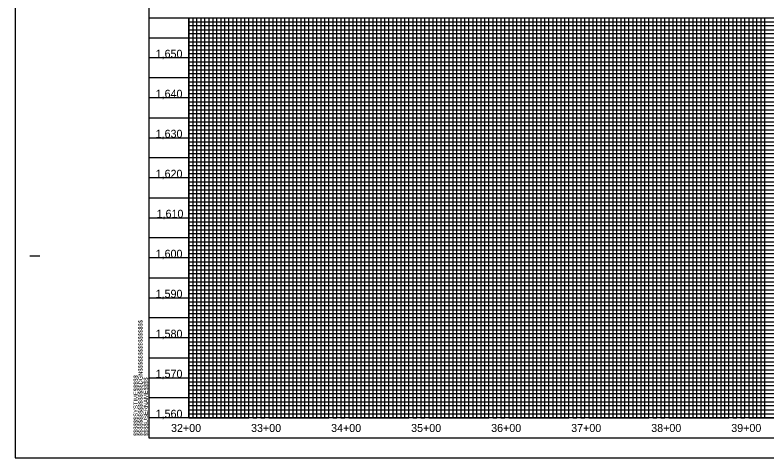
# Model space of a CAD drawing. Extents: x 502400 to 509344, y 448070 to 484209.
# Drawn here: x 505602 to 506542, y 483109 to 483662 of the extents above; entities that cross this region are included whole.
import ezdxf

# ---------------------------------------------------------------- set-up
doc = ezdxf.new("R2010")
doc.units = 0
for name, color, linetype in [('Exist Vertical Profile Vertical Axis Label', 7, 'Continuous'), ('Sheet Layout Profile Border Port 2', 7, 'Continuous'), ('Sheet Plot Border Outside CELL', 7, 'Continuous'), ('Sheet Profile CELL', 7, 'Continuous'), ('Sheet Profile Grid Major CELL', 7, 'Continuous'), ('Sheet Profile Grid Middle CELL', 7, 'Continuous'), ('Sheet Profile Grid Minor CELL', 7, 'Continuous')]:
    doc.layers.add(name, color=color, linetype=linetype)

msp = doc.modelspace()

# ---------------------------------------------------------------- linework, layer by layer
at = {"layer": 'Sheet Layout Profile Border Port 2'}
msp.add_lwpolyline([(505819.08, 483658.71), (507219.08, 483658.71), (507219.08, 483158.71), (505819.08, 483158.71)], close=True, dxfattribs=at)
at = {"layer": 'Sheet Plot Border Outside CELL'}
msp.add_lwpolyline([(505602.08, 483108.71), (507286.08, 483108.71), (507286.08, 484208.71), (505602.08, 484208.71)], close=True, dxfattribs=at)
at = {"layer": 'Sheet Profile CELL'}
for p, q in [((505769.08, 483658.71), (507269.08, 483658.71)), ((505620.58, 483361.21), (505633.08, 483361.21)), ((507269.08, 483158.71), (505769.08, 483158.71)), ((505769.08, 483133.71), (507269.08, 483133.71)), ((505769.08, 483133.71), (505769.08, 483133.71)), ((505769.08, 483133.71), (505769.08, 483133.71)), ((505769.08, 483133.71), (505769.08, 483133.71)), ((505769.08, 483133.71), (505769.08, 483133.71)), ((505769.08, 483133.71), (505769.08, 483133.71)), ((505769.08, 483133.71), (505769.08, 483133.71)), ((505769.08, 483133.71), (505769.08, 483133.71))]:
    msp.add_line(p, q, dxfattribs=at)
msp.add_lwpolyline([(507269.08, 484183.71), (505769.08, 484183.71), (505769.08, 483133.71), (507269.08, 483133.71)], close=True, dxfattribs=at)
msp.add_lwpolyline([(505806.58, 483133.71), (505806.58, 483133.71)], dxfattribs=at)
at = {"layer": 'Sheet Profile Grid Major CELL'}
for p, q in [((506269.08, 483658.71), (506319.08, 483658.71)), ((506369.08, 483658.71), (506419.08, 483658.71)), ((506469.08, 483658.71), (506519.08, 483658.71))]:
    msp.add_line(p, q, dxfattribs=at)
for points in [[(505819.08, 483658.71), (505819.08, 483158.71), (505869.08, 483158.71), (505869.08, 483658.71), (505919.08, 483658.71), (505919.08, 483158.71), (505969.08, 483158.71), (505969.08, 483658.71), (506019.08, 483658.71), (506019.08, 483158.71), (506069.08, 483158.71), (506069.08, 483658.71), (506119.08, 483658.71), (506119.08, 483158.71), (506169.08, 483158.71), (506169.08, 483658.71), (506219.08, 483658.71), (506219.08, 483158.71), (506269.08, 483158.71), (506269.08, 483658.71), (506319.08, 483658.71), (506319.08, 483158.71), (506369.08, 483158.71), (506369.08, 483658.71), (506419.08, 483658.71), (506419.08, 483158.71), (506469.08, 483158.71), (506469.08, 483658.71), (506519.08, 483658.71), (506519.08, 483158.71), (506569.08, 483158.71)], [(505819.08, 483658.71), (505819.08, 483158.71), (505869.08, 483158.71), (505869.08, 483658.71), (505919.08, 483658.71), (505919.08, 483158.71), (505969.08, 483158.71), (505969.08, 483658.71), (506019.08, 483658.71), (506019.08, 483158.71), (506069.08, 483158.71), (506069.08, 483658.71), (506119.08, 483658.71), (506119.08, 483158.71), (506169.08, 483158.71), (506169.08, 483658.71), (506219.08, 483658.71), (506219.08, 483158.71), (506269.08, 483158.71), (506269.08, 483658.71), (506319.08, 483658.71), (506319.08, 483158.71), (506369.08, 483158.71), (506369.08, 483658.71), (506419.08, 483658.71), (506419.08, 483158.71), (506469.08, 483158.71), (506469.08, 483658.71), (506519.08, 483658.71), (506519.08, 483158.71), (506569.08, 483158.71)], [(507269.08, 483608.71), (505769.08, 483608.71)], [(507269.08, 483558.71), (505769.08, 483558.71), (505769.08, 483508.71), (507269.08, 483508.71)], [(507269.08, 483458.71), (505769.08, 483458.71), (505769.08, 483408.71), (507269.08, 483408.71)], [(507269.08, 483358.71), (505769.08, 483358.71), (505769.08, 483308.71), (507269.08, 483308.71)], [(507269.08, 483258.71), (505769.08, 483258.71), (505769.08, 483258.71), (505769.08, 483208.71), (507269.08, 483208.71)], [(507269.08, 483158.71), (505769.08, 483158.71)]]:
    msp.add_lwpolyline(points, dxfattribs=at)
at = {"layer": 'Sheet Profile Grid Middle CELL'}
for points in [[(505794.08, 483658.71), (505844.08, 483658.71), (505844.08, 483158.71), (505894.08, 483158.71), (505894.08, 483658.71), (505944.08, 483658.71), (505944.08, 483158.71), (505994.08, 483158.71), (505994.08, 483658.71), (506044.08, 483658.71), (506044.08, 483158.71), (506094.08, 483158.71), (506094.08, 483658.71), (506144.08, 483658.71), (506144.08, 483158.71), (506194.08, 483158.71), (506194.08, 483658.71), (506244.08, 483658.71), (506244.08, 483158.71), (506294.08, 483158.71), (506294.08, 483658.71), (506344.08, 483658.71), (506344.08, 483158.71), (506394.08, 483158.71), (506394.08, 483158.71), (506394.08, 483658.71), (506444.08, 483658.71), (506444.08, 483158.71), (506494.08, 483158.71), (506494.08, 483658.71), (506544.08, 483658.71)], [(505769.08, 483633.71), (507269.08, 483633.71)], [(507269.08, 483583.71), (505769.08, 483583.71), (505769.08, 483533.71), (507269.08, 483533.71)], [(507269.08, 483483.71), (505769.08, 483483.71), (505769.08, 483433.71), (507269.08, 483433.71)], [(507269.08, 483383.71), (505769.08, 483383.71), (505769.08, 483333.71), (507269.08, 483333.71)], [(507269.08, 483283.71), (505769.08, 483283.71), (505769.08, 483233.71), (507269.08, 483233.71)], [(507269.08, 483183.71), (505769.08, 483183.71)]]:
    msp.add_lwpolyline(points, dxfattribs=at)
at = {"layer": 'Sheet Profile Grid Minor CELL'}
for p, q in [((505819.08, 483653.71), (507219.08, 483653.71)), ((507219.08, 483648.71), (505819.08, 483648.71)), ((505819.08, 483643.71), (507219.08, 483643.71)), ((507219.08, 483638.71), (505819.08, 483638.71)), ((505819.08, 483628.71), (507219.08, 483628.71)), ((507219.08, 483623.71), (505819.08, 483623.71)), ((505819.08, 483618.71), (507219.08, 483618.71)), ((507219.08, 483613.71), (505819.08, 483613.71)), ((505819.08, 483603.71), (507219.08, 483603.71)), ((507219.08, 483598.71), (505819.08, 483598.71)), ((505819.08, 483593.71), (507219.08, 483593.71)), ((507219.08, 483588.71), (505819.08, 483588.71)), ((505819.08, 483578.71), (507219.08, 483578.71)), ((507219.08, 483573.71), (505819.08, 483573.71)), ((505819.08, 483568.71), (507219.08, 483568.71)), ((507219.08, 483563.71), (505819.08, 483563.71)), ((505819.08, 483553.71), (507219.08, 483553.71)), ((507219.08, 483548.71), (505819.08, 483548.71)), ((505819.08, 483543.71), (507219.08, 483543.71)), ((507219.08, 483538.71), (505819.08, 483538.71)), ((505819.08, 483528.71), (507219.08, 483528.71)), ((507219.08, 483523.71), (505819.08, 483523.71)), ((505819.08, 483518.71), (507219.08, 483518.71)), ((507219.08, 483513.71), (505819.08, 483513.71)), ((505819.08, 483503.71), (507219.08, 483503.71)), ((507219.08, 483498.71), (505819.08, 483498.71)), ((505819.08, 483493.71), (507219.08, 483493.71)), ((507219.08, 483488.71), (505819.08, 483488.71)), ((505819.08, 483478.71), (507219.08, 483478.71)), ((507219.08, 483473.71), (505819.08, 483473.71)), ((505819.08, 483468.71), (507219.08, 483468.71)), ((507219.08, 483463.71), (505819.08, 483463.86)), ((505819.08, 483453.71), (507219.08, 483453.71)), ((507219.08, 483448.71), (505819.08, 483448.71)), ((505819.08, 483443.71), (507219.08, 483443.71)), ((507219.08, 483438.71), (505819.08, 483438.71)), ((505819.08, 483428.71), (507219.08, 483428.71)), ((507219.08, 483423.71), (505819.08, 483423.71)), ((505819.08, 483418.71), (507219.08, 483418.71)), ((507219.08, 483413.71), (505819.08, 483413.71)), ((505819.08, 483403.71), (507219.08, 483403.71)), ((507219.08, 483398.71), (505819.08, 483398.71)), ((505819.08, 483393.71), (507219.08, 483393.71)), ((507219.08, 483388.71), (505819.08, 483388.71)), ((505819.08, 483378.71), (507219.08, 483378.71)), ((507219.08, 483373.71), (505819.08, 483373.71)), ((505819.08, 483368.71), (507219.08, 483368.71)), ((507219.08, 483363.71), (505819.08, 483363.71)), ((505819.08, 483353.71), (507219.08, 483353.71)), ((507219.08, 483348.71), (505819.08, 483348.71)), ((505819.08, 483343.71), (507219.08, 483343.71)), ((507219.08, 483338.71), (505819.08, 483338.71)), ((505819.08, 483328.71), (507219.08, 483328.71)), ((507219.08, 483323.71), (505819.08, 483323.71)), ((505819.08, 483318.71), (507219.08, 483318.71)), ((507219.08, 483313.71), (505819.08, 483313.71)), ((505819.08, 483303.71), (507219.08, 483303.71)), ((507219.08, 483298.71), (505819.08, 483298.71)), ((505819.08, 483293.71), (507219.08, 483293.71)), ((507219.08, 483288.71), (505819.08, 483288.71)), ((505819.08, 483278.71), (507219.08, 483278.71)), ((507219.08, 483273.71), (505819.08, 483273.71)), ((505819.08, 483268.71), (507219.08, 483268.71)), ((507219.08, 483263.71), (505819.08, 483263.71)), ((505819.08, 483253.71), (507219.08, 483253.71)), ((507219.08, 483248.71), (505819.08, 483248.71)), ((505819.08, 483243.71), (507219.08, 483243.71)), ((507154.08, 483238.71), (505819.08, 483238.71)), ((505819.08, 483228.71), (507219.08, 483228.71)), ((507219.08, 483223.71), (505819.08, 483223.71)), ((505819.08, 483218.71), (507219.08, 483218.71)), ((507219.08, 483213.71), (505819.08, 483213.71)), ((505819.08, 483203.71), (507219.08, 483203.71)), ((507219.08, 483198.71), (505819.08, 483198.71)), ((505819.08, 483193.71), (507219.08, 483193.71)), ((507219.08, 483188.71), (505819.08, 483188.71)), ((505819.08, 483178.71), (507219.08, 483178.71)), ((507219.08, 483173.71), (505819.08, 483173.71)), ((505819.08, 483168.71), (507219.08, 483168.71)), ((505819.08, 483163.71), (507219.08, 483163.71))]:
    msp.add_line(p, q, dxfattribs=at)
for points in [[(505819.08, 483658.71), (505824.08, 483658.71), (505824.08, 483158.71), (505829.08, 483158.71), (505829.08, 483658.71), (505834.08, 483658.71), (505834.08, 483158.71), (505839.08, 483158.71), (505839.08, 483658.71), (505849.08, 483658.71), (505849.08, 483158.71), (505854.08, 483158.71), (505854.08, 483658.71), (505859.08, 483658.71), (505859.08, 483158.71), (505864.08, 483158.71), (505874.08, 483158.71), (505879.08, 483158.71), (505879.08, 483658.71), (505884.08, 483658.71), (505884.08, 483158.71), (505889.08, 483158.71), (505889.08, 483658.71), (505899.08, 483658.71), (505899.08, 483158.71), (505904.08, 483158.71), (505904.08, 483658.71), (505909.08, 483658.71), (505909.08, 483158.71), (505914.08, 483158.71), (505914.08, 483658.71), (505924.08, 483658.71), (505924.08, 483158.71), (505929.08, 483158.71), (505929.08, 483658.71), (505934.08, 483658.71), (505934.08, 483158.71), (505939.08, 483158.71), (505939.08, 483658.71), (505949.08, 483658.71), (505949.08, 483158.71), (505954.08, 483158.71), (505954.08, 483658.71), (505959.08, 483658.71), (505959.08, 483158.71), (505964.08, 483158.71), (505964.08, 483658.71), (505974.08, 483658.71), (505974.08, 483158.71), (505979.08, 483158.71), (505979.08, 483658.71), (505984.08, 483658.71), (505984.08, 483158.71), (505989.08, 483158.71), (505989.08, 483658.71), (505999.08, 483658.71), (505999.08, 483158.71), (506004.08, 483158.71), (506004.08, 483658.71), (506009.08, 483658.71), (506009.08, 483158.71), (506014.08, 483158.71), (506014.08, 483658.71), (506024.08, 483658.71), (506024.08, 483158.71), (506029.08, 483158.71), (506029.08, 483658.71), (506034.08, 483658.71), (506034.08, 483158.71)], [(505864.08, 483158.71), (505864.08, 483658.71), (505874.08, 483658.71), (505874.08, 483158.71)], [(506034.08, 483158.71), (506039.08, 483158.71), (506039.08, 483658.71), (506049.08, 483658.71), (506049.08, 483158.71), (506054.08, 483158.71), (506054.08, 483658.71), (506059.08, 483658.71), (506059.08, 483158.71), (506064.08, 483158.71), (506064.08, 483658.71), (506074.08, 483658.71), (506074.08, 483158.71), (506079.08, 483158.71), (506079.08, 483658.71), (506084.08, 483658.71), (506084.08, 483158.71), (506089.08, 483158.71), (506089.08, 483658.71), (506099.08, 483658.71), (506099.08, 483158.71), (506104.08, 483158.71), (506104.08, 483658.71), (506109.08, 483658.71), (506109.08, 483158.71), (506114.08, 483158.71), (506114.08, 483658.71), (506124.08, 483658.71), (506124.08, 483158.71), (506129.08, 483158.71), (506129.08, 483658.71), (506134.08, 483658.71), (506134.08, 483158.71), (506139.08, 483158.71), (506139.08, 483658.71), (506149.08, 483658.71), (506149.08, 483158.71), (506154.08, 483158.71), (506154.08, 483658.71), (506159.08, 483658.71), (506159.08, 483158.71), (506164.08, 483158.71), (506164.08, 483658.71), (506174.08, 483658.71), (506174.08, 483158.71), (506179.08, 483158.71), (506179.08, 483658.71), (506184.08, 483658.71), (506184.08, 483158.71), (506189.08, 483158.71), (506189.08, 483658.71), (506199.08, 483658.71), (506199.08, 483158.71), (506204.08, 483158.71), (506204.08, 483658.71), (506209.08, 483658.71), (506209.08, 483158.71), (506214.08, 483158.71), (506214.08, 483658.71), (506224.08, 483658.71), (506224.08, 483158.71), (506229.08, 483158.71), (506229.08, 483658.71), (506234.08, 483658.71), (506234.08, 483158.71), (506239.08, 483158.71), (506239.08, 483658.71), (506249.08, 483658.71), (506249.08, 483158.71), (506254.08, 483158.71), (506254.08, 483658.71), (506259.08, 483658.71), (506259.08, 483158.71), (506264.08, 483158.71), (506264.08, 483658.71), (506274.08, 483658.71), (506274.08, 483158.71), (506279.08, 483158.71), (506279.08, 483658.71), (506284.08, 483658.71), (506284.08, 483158.71), (506289.08, 483158.71), (506289.08, 483658.71), (506299.08, 483658.71), (506299.08, 483158.71), (506304.08, 483158.71), (506304.08, 483658.71), (506309.08, 483658.71), (506309.08, 483158.71), (506314.08, 483158.71), (506314.08, 483658.71), (506324.08, 483658.71), (506324.08, 483158.71), (506329.08, 483158.71), (506329.08, 483658.71), (506334.08, 483658.71), (506334.08, 483158.71), (506339.08, 483158.71), (506339.08, 483658.71), (506349.08, 483658.71)], [(506349.08, 483658.71), (506349.08, 483158.71), (506354.08, 483158.71), (506354.08, 483658.71), (506359.08, 483658.71), (506359.08, 483158.71), (506364.08, 483158.71), (506364.08, 483658.71), (506374.08, 483658.71), (506374.08, 483158.71), (506379.08, 483158.71), (506379.08, 483658.71), (506384.08, 483658.71), (506384.08, 483158.71), (506389.08, 483158.71), (506389.08, 483658.71), (506399.08, 483658.71), (506399.08, 483158.71), (506404.08, 483158.71), (506404.08, 483658.71), (506409.08, 483658.71), (506409.08, 483158.71), (506414.08, 483158.71), (506414.08, 483658.71), (506424.08, 483658.71), (506424.08, 483158.71), (506429.08, 483158.71), (506429.08, 483658.71), (506434.08, 483658.71), (506434.08, 483158.71), (506439.08, 483158.71), (506439.08, 483658.71), (506449.08, 483658.71), (506449.08, 483158.71), (506454.08, 483158.71), (506454.08, 483658.71), (506459.08, 483658.71), (506459.08, 483158.71), (506464.08, 483158.71), (506464.08, 483658.71), (506474.08, 483658.71), (506474.08, 483158.71), (506474.08, 483158.71), (506479.08, 483158.71), (506479.08, 483658.71), (506484.08, 483658.71), (506484.08, 483158.71), (506489.08, 483158.71), (506489.08, 483658.71), (506499.08, 483658.71), (506499.08, 483158.71), (506504.08, 483158.71), (506504.08, 483658.71), (506509.08, 483658.71), (506509.08, 483158.71), (506514.08, 483158.71), (506514.08, 483658.71), (506524.08, 483658.71), (506524.08, 483158.71), (506529.08, 483158.71), (506529.08, 483658.71), (506534.08, 483658.71), (506534.08, 483158.71), (506539.08, 483158.71), (506539.08, 483658.71), (506549.08, 483658.71)]]:
    msp.add_lwpolyline(points, dxfattribs=at)

# ---------------------------------------------------------------- texts
at = {"layer": 'Exist Vertical Profile Vertical Axis Label'}
for s, p in [('1,650', (505777.81, 483608.96)), ('1,640', (505777.81, 483558.96)), ('1,630', (505777.81, 483508.96)), ('1,620', (505777.81, 483458.96)), ('1,610', (505779, 483408.96)), ('1,600', (505777.81, 483358.96)), ('1,590', (505777.81, 483308.96)), ('1,580', (505777.81, 483258.96)), ('1,570', (505777.81, 483208.96)), ('1,560', (505777.81, 483158.96)), ('32+00', (505797.01, 483141.21)), ('33+00', (505897.01, 483141.21)), ('34+00', (505997.01, 483141.21)), ('35+00', (506097.01, 483141.21)), ('36+00', (506197.01, 483141.21)), ('37+00', (506297.01, 483141.21)), ('38+00', (506397.01, 483141.21)), ('39+00', (506497.01, 483141.21))]:
    msp.add_text(s, height=10, dxfattribs=at).set_placement(p)
at = {"layer": 'Sheet Profile CELL'}
for s, p in [('$$$$$$$$$$$$$$$$DGN$$$$$$$$$$$$$$$$', (505761.44, 483136.09)), ('$$$$$$SYSTIME$$$$$', (505755.39, 483136.09)), ('$$$$USERNAME$$$$', (505768.02, 483136.1))]:
    msp.add_text(s, height=5.25, rotation=90, dxfattribs=at).set_placement(p)

doc.saveas('drawing.dxf')
